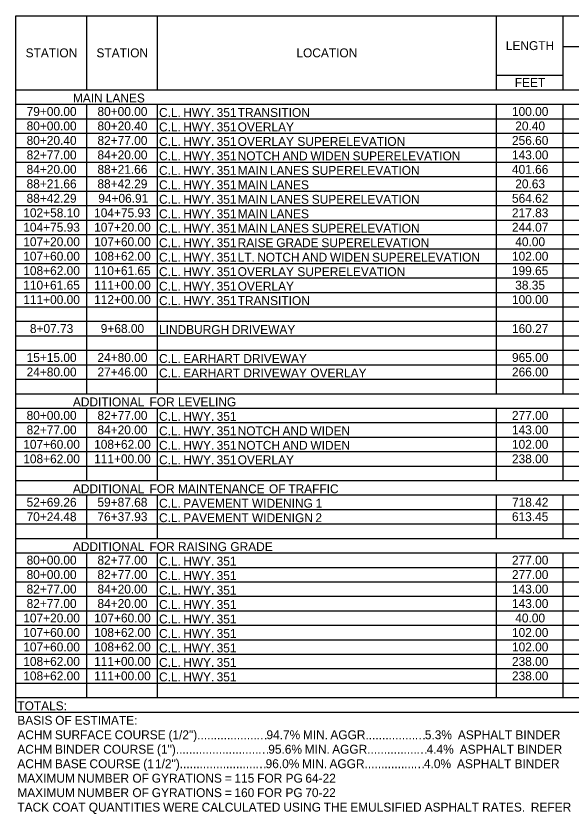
# Model space of a CAD drawing. Extents: x 1197542 to 1207068, y 230488 to 237324.
# Drawn here: x 1201719 to 1202093, y 231730 to 232267 of the extents above; entities that cross this region are included whole.
import ezdxf

# ---------------------------------------------------------------- set-up
doc = ezdxf.new("R2010")
doc.units = 0
doc.layers.add('Default', color=7, linetype='Continuous')

msp = doc.modelspace()

# ---------------------------------------------------------------- linework, layer by layer
at = {"layer": 'Default'}
for p, q in [((1201719.44, 232267.45), (1203261.96, 232267.45)), ((1201719.44, 231798.48), (1201719.44, 232267.45)), ((1201719.44, 231798.48), (1201719.44, 232267.45)), ((1201767.17, 232217.73), (1201767.17, 232267.45)), ((1201814.91, 232217.73), (1201814.91, 232267.45)), ((1202043.29, 232217.73), (1202043.29, 232267.45)), ((1202088.22, 232217.73), (1202088.22, 232267.45)), ((1202088.22, 232246.98), (1203261.96, 232246.98)), ((1202043.29, 232227.48), (1202088.22, 232227.48)), ((1202088.22, 232217.73), (1202088.22, 232227.48)), ((1201719.44, 232217.73), (1203261.96, 232217.73)), ((1202088.22, 232217.73), (1202223, 232217.73)), ((1201719.44, 232207.98), (1203261.96, 232207.98)), ((1201767.17, 232012.98), (1201767.17, 232207.98)), ((1201767.17, 232012.98), (1201767.17, 232207.98)), ((1201814.91, 232012.98), (1201814.91, 232207.98)), ((1201814.91, 232012.98), (1201814.91, 232207.98)), ((1202043.29, 232012.98), (1202043.29, 232207.98)), ((1202043.29, 232012.98), (1202043.29, 232207.98)), ((1202088.22, 232012.98), (1202088.22, 232207.98)), ((1202088.22, 232012.98), (1202088.22, 232207.98)), ((1201719.44, 232198.23), (1203261.96, 232198.23)), ((1201719.44, 232188.48), (1203261.96, 232188.48)), ((1201719.44, 232178.73), (1203261.96, 232178.73)), ((1201719.44, 232168.98), (1203261.96, 232168.98)), ((1201719.44, 232159.23), (1203261.96, 232159.23)), ((1201719.44, 232149.48), (1203261.96, 232149.48)), ((1201719.44, 232139.73), (1203261.96, 232139.73)), ((1201719.44, 232129.98), (1203261.96, 232129.98)), ((1201719.44, 232120.23), (1203261.96, 232120.23)), ((1201719.44, 232110.48), (1203261.96, 232110.48)), ((1201719.44, 232100.73), (1203261.96, 232100.73)), ((1201719.44, 232090.98), (1203261.96, 232090.98)), ((1201719.44, 232081.23), (1203261.96, 232081.23)), ((1201719.44, 232071.48), (1203261.96, 232071.48)), ((1201719.44, 232061.73), (1203261.96, 232061.73)), ((1201719.44, 232051.98), (1203261.96, 232051.98)), ((1201719.44, 232042.23), (1203261.96, 232042.23)), ((1201719.44, 232032.48), (1203261.96, 232032.48)), ((1201719.44, 232022.73), (1203261.96, 232022.73)), ((1201719.44, 232012.98), (1202992.4, 232012.98)), ((1201719.44, 232012.98), (1203261.96, 232012.98)), ((1201719.44, 232003.23), (1203261.96, 232003.23)), ((1201767.17, 231954.48), (1201767.17, 232003.23)), ((1201767.17, 231954.48), (1201767.17, 232003.23)), ((1201814.91, 231954.48), (1201814.91, 232003.23)), ((1201814.91, 231954.48), (1201814.91, 232003.23)), ((1202043.29, 231954.48), (1202043.29, 232003.23)), ((1202043.29, 231954.48), (1202043.29, 232003.23)), ((1202088.22, 231954.48), (1202088.22, 232003.23)), ((1202088.22, 231954.48), (1202088.22, 232003.23)), ((1201719.44, 231993.48), (1203261.96, 231993.48)), ((1201719.44, 231983.73), (1203261.96, 231983.73)), ((1201719.44, 231973.98), (1203261.96, 231973.98)), ((1201719.44, 231964.23), (1203261.96, 231964.23)), ((1201719.44, 231954.48), (1203261.96, 231954.48)), ((1201719.44, 231954.48), (1203261.96, 231954.48)), ((1201719.44, 231944.73), (1203261.96, 231944.73)), ((1201767.17, 231915.48), (1201767.17, 231944.73)), ((1201767.17, 231915.48), (1201767.17, 231944.73)), ((1201814.91, 231915.48), (1201814.91, 231944.73)), ((1201814.91, 231915.48), (1201814.91, 231944.73)), ((1202043.29, 231915.48), (1202043.29, 231944.73)), ((1202043.29, 231915.48), (1202043.29, 231944.73)), ((1202088.22, 231915.48), (1202088.22, 231944.73)), ((1202088.22, 231915.48), (1202088.22, 231944.73)), ((1201719.44, 231934.98), (1203261.96, 231934.98)), ((1201719.44, 231925.23), (1203261.96, 231925.23)), ((1201719.44, 231915.48), (1202992.4, 231915.48)), ((1201719.44, 231915.48), (1203261.96, 231915.48)), ((1201719.44, 231905.73), (1203261.96, 231905.73)), ((1201767.17, 231808.23), (1201767.17, 231905.73)), ((1201767.17, 231808.23), (1201767.17, 231905.73)), ((1201814.91, 231808.23), (1201814.91, 231905.73)), ((1201814.91, 231808.23), (1201814.91, 231905.73)), ((1202043.29, 231808.23), (1202043.29, 231905.73)), ((1202043.29, 231808.23), (1202043.29, 231905.73)), ((1202088.22, 231808.23), (1202088.22, 231905.73)), ((1202088.22, 231808.23), (1202088.22, 231905.73)), ((1201719.44, 231895.98), (1203261.96, 231895.98)), ((1201719.44, 231886.23), (1203261.96, 231886.23)), ((1201719.44, 231876.48), (1203261.96, 231876.48)), ((1201719.44, 231866.73), (1203261.96, 231866.73)), ((1201719.44, 231856.98), (1203261.96, 231856.98)), ((1201719.44, 231847.23), (1203261.96, 231847.23)), ((1201719.44, 231837.48), (1203261.96, 231837.48)), ((1201719.44, 231827.73), (1203261.96, 231827.73)), ((1201719.44, 231817.98), (1203261.96, 231817.98)), ((1201719.44, 231808.23), (1203261.96, 231808.23)), ((1201719.44, 231808.23), (1203261.96, 231808.23)), ((1201719.44, 231798.48), (1203261.96, 231798.48))]:
    msp.add_line(p, q, dxfattribs=at)

# ---------------------------------------------------------------- texts
for s, p in [('LENGTH', (1202049.52, 232244.47)), ('STATION', (1201725.96, 232239.59)), ('STATION', (1201773.7, 232239.59)), ('LOCATION', (1201908.41, 232239.59)), ('FEET', (1202055.55, 232219.6)), ('MAIN', (1201757.81, 232209.18)), (' LANES', (1201777.73, 232209.18)), ('79+00.00', (1201726.61, 232200.1)), ('80+00.00', (1201774.35, 232200.1)), ('C.L.', (1201815.84, 232199.43)), (' HWY.', (1201829.9, 232199.43)), (' 351', (1201852.44, 232199.43)), (' TRANSITION', (1201866.62, 232199.43)), ('100.00', (1202053.65, 232200.1)), ('80+00.00', (1201726.61, 232190.35)), ('80+20.40', (1201774.35, 232190.35)), ('C.L.', (1201815.84, 232189.68)), (' HWY.', (1201829.9, 232189.68)), (' 351', (1201852.44, 232189.68)), (' OVERLAY', (1201866.62, 232189.68)), ('20.40', (1202055.88, 232190.35)), ('80+20.40', (1201726.61, 232180.6)), ('82+77.00', (1201774.35, 232180.6)), ('C.L.', (1201815.84, 232179.93)), (' HWY.', (1201829.9, 232179.93)), (' 351', (1201852.44, 232179.93)), (' OVERLAY', (1201866.62, 232179.93)), (' SUPERELEVATION', (1201906.81, 232179.93)), ('256.60', (1202053.65, 232180.6)), ('82+77.00', (1201726.61, 232170.85)), ('84+20.00', (1201774.35, 232170.85)), ('C.L.', (1201815.84, 232170.18)), (' HWY.', (1201829.9, 232170.18)), (' 351', (1201852.44, 232170.18)), (' NOTCH', (1201866.62, 232170.18)), (' AND', (1201896.82, 232170.18)), (' WIDEN', (1201915.62, 232170.18)), (' SUPERELEVATION', (1201944.02, 232170.18)), ('143.00', (1202053.65, 232170.85)), ('84+20.00', (1201726.61, 232161.1)), ('88+21.66', (1201774.34, 232161.1)), ('401.66', (1202053.64, 232161.1)), ('C.L.', (1201815.84, 232160.43)), (' HWY.', (1201829.9, 232160.43)), (' 351', (1201852.44, 232160.43)), (' MAIN', (1201866.62, 232160.43)), (' LANES', (1201888.31, 232160.43)), (' SUPERELEVATION', (1201916.52, 232160.43)), ('88+21.66', (1201726.6, 232151.35)), ('88+42.29', (1201774.33, 232151.35)), ('C.L.', (1201815.84, 232150.68)), (' HWY.', (1201829.9, 232150.68)), (' 351', (1201852.44, 232150.68)), (' MAIN', (1201866.62, 232150.68)), (' LANES', (1201888.31, 232150.68)), ('20.63', (1202055.87, 232151.35)), ('88+42.29', (1201726.59, 232141.6)), ('94+06.91', (1201774.89, 232141.6)), ('C.L.', (1201815.84, 232140.93)), (' HWY.', (1201829.9, 232140.93)), (' 351', (1201852.44, 232140.93)), (' MAIN', (1201866.62, 232140.93)), (' LANES', (1201888.31, 232140.93)), (' SUPERELEVATION', (1201916.52, 232140.93)), ('564.62', (1202053.67, 232141.6)), ('102+58.10', (1201724.37, 232131.85)), ('104+75.93', (1201772.1, 232131.85)), ('C.L.', (1201815.84, 232131.18)), (' HWY.', (1201829.9, 232131.18)), (' 351', (1201852.44, 232131.18)), (' MAIN', (1201866.62, 232131.18)), (' LANES', (1201888.31, 232131.18)), ('217.83', (1202053.64, 232131.85)), ('104+75.93', (1201724.36, 232122.1)), ('107+20.00', (1201772.11, 232122.1)), ('C.L.', (1201815.84, 232121.43)), (' HWY.', (1201829.9, 232121.43)), (' 351', (1201852.44, 232121.43)), (' MAIN', (1201866.62, 232121.43)), (' LANES', (1201888.31, 232121.43)), (' SUPERELEVATION', (1201916.52, 232121.43)), ('244.07', (1202053.64, 232122.1)), ('107+20.00', (1201724.37, 232112.35)), ('107+60.00', (1201772.11, 232112.35)), ('C.L.', (1201815.84, 232111.68)), (' HWY.', (1201829.9, 232111.68)), (' 351', (1201852.44, 232111.68)), (' RAISE', (1201866.62, 232111.68)), (' GRADE', (1201892.58, 232111.68)), (' SUPERELEVATION', (1201923.01, 232111.68)), ('40.00', (1202055.88, 232112.35)), ('107+60.00', (1201724.37, 232102.6)), ('108+62.00', (1201772.11, 232102.6)), ('102.00', (1202053.65, 232102.6)), ('C.L.', (1201815.84, 232101.93)), (' HWY.', (1201829.9, 232101.93)), (' 351', (1201852.44, 232101.93)), (' LT.', (1201866.62, 232101.93)), (' NOTCH', (1201879.77, 232101.93)), (' AND', (1201909.98, 232101.93)), (' WIDEN', (1201928.77, 232101.93)), (' SUPERELEVATION', (1201957.17, 232101.93)), ('108+62.00', (1201724.37, 232092.85)), ('110+61.65', (1201772.08, 232092.85)), ('C.L.', (1201815.84, 232092.18)), (' HWY.', (1201829.9, 232092.18)), (' 351', (1201852.44, 232092.18)), (' OVERLAY', (1201866.62, 232092.18)), (' SUPERELEVATION', (1201906.81, 232092.18)), ('199.65', (1202053.61, 232092.85)), ('110+61.65', (1201724.34, 232083.1)), ('111+00.00', (1201772.11, 232083.1)), ('C.L.', (1201815.84, 232082.43)), (' HWY.', (1201829.9, 232082.43)), (' 351', (1201852.44, 232082.43)), (' OVERLAY', (1201866.62, 232082.43)), ('38.35', (1202055.85, 232083.1)), ('111+00.00', (1201724.37, 232073.35)), ('112+00.00', (1201772.11, 232073.35)), ('C.L.', (1201815.84, 232072.68)), (' HWY.', (1201829.9, 232072.68)), (' 351', (1201852.44, 232072.68)), (' TRANSITION', (1201866.62, 232072.68)), ('100.00', (1202053.65, 232073.35)), ('8+07.73', (1201728.84, 232053.85)), ('9+68.00', (1201776.58, 232053.85)), ('160.27', (1202053.64, 232053.85)), ('LINDBURGH', (1201815.84, 232053.18)), (' DRIVEWAY', (1201862.6, 232053.18)), ('15+15.00', (1201726.61, 232034.35)), ('24+80.00', (1201774.35, 232034.35)), ('C.L.', (1201815.84, 232033.68)), (' EARHART', (1201829.9, 232033.68)), (' DRIVEWAY', (1201870.43, 232033.68)), ('965.00', (1202053.65, 232034.35)), ('24+80.00', (1201726.61, 232024.6)), ('27+46.00', (1201774.35, 232024.6)), ('C.L.', (1201815.84, 232023.93)), (' EARHART', (1201829.9, 232023.93)), (' DRIVEWAY', (1201870.43, 232023.93)), (' OVERLAY', (1201915.54, 232023.93)), ('266.00', (1202053.65, 232024.6)), ('ADDITIONAL', (1201757.81, 232004.43)), (' FOR', (1201807.2, 232004.43)), (' LEVELING', (1201826.38, 232004.43)), ('80+00.00', (1201726.61, 231995.35)), ('82+77.00', (1201774.35, 231995.35)), ('C.L.', (1201815.84, 231994.68)), (' HWY.', (1201829.9, 231994.68)), (' 351', (1201852.44, 231994.68)), ('277.00', (1202053.65, 231995.35)), ('82+77.00', (1201726.61, 231985.6)), ('84+20.00', (1201774.35, 231985.6)), ('C.L.', (1201815.84, 231984.93)), (' HWY.', (1201829.9, 231984.93)), (' 351', (1201852.44, 231984.93)), (' NOTCH', (1201866.62, 231984.93)), (' AND', (1201896.82, 231984.93)), (' WIDEN', (1201915.62, 231984.93)), ('143.00', (1202053.65, 231985.6)), ('107+60.00', (1201724.37, 231975.85)), ('108+62.00', (1201772.11, 231975.85)), ('C.L.', (1201815.84, 231975.18)), (' HWY.', (1201829.9, 231975.18)), (' 351', (1201852.44, 231975.18)), (' NOTCH', (1201866.62, 231975.18)), (' AND', (1201896.82, 231975.18)), (' WIDEN', (1201915.62, 231975.18)), ('102.00', (1202053.65, 231975.85)), ('108+62.00', (1201724.37, 231966.1)), ('111+00.00', (1201772.11, 231966.1)), ('C.L.', (1201815.84, 231965.43)), (' HWY.', (1201829.9, 231965.43)), (' 351', (1201852.44, 231965.43)), (' OVERLAY', (1201866.62, 231965.43)), ('238.00', (1202053.65, 231966.1)), ('ADDITIONAL', (1201757.81, 231945.93)), (' FOR', (1201807.2, 231945.93)), (' MAINTENANCE', (1201826.38, 231945.93)), (' OF', (1201887.69, 231945.93)), (' TRAFFIC', (1201900.73, 231945.93)), ('52+69.26', (1201726.6, 231936.85)), ('59+87.68', (1201774.33, 231936.85)), ('C.L.', (1201815.84, 231936.18)), (' PAVEMENT', (1201829.9, 231936.18)), (' WIDENING', (1201876.25, 231936.18)), (' 1', (1201919.11, 231936.18)), ('718.42', (1202053.67, 231936.85)), ('70+24.48', (1201726.59, 231927.1)), ('76+37.93', (1201774.34, 231927.1)), ('C.L.', (1201815.84, 231926.43)), (' PAVEMENT', (1201829.9, 231926.43)), (' WIDENIGN', (1201876.25, 231926.43)), (' 2', (1201918.96, 231926.43)), ('613.45', (1202053.61, 231927.1)), ('ADDITIONAL', (1201757.81, 231906.93)), (' FOR', (1201807.2, 231906.93)), (' RAISING', (1201826.38, 231906.93)), (' GRADE', (1201861.67, 231906.93)), ('80+00.00', (1201726.61, 231897.85)), ('82+77.00', (1201774.35, 231897.85)), ('277.00', (1202053.65, 231897.85)), ('C.L.', (1201815.84, 231897.18)), (' HWY.', (1201829.9, 231897.18)), (' 351', (1201852.44, 231897.18)), ('80+00.00', (1201726.61, 231888.1)), ('82+77.00', (1201774.35, 231888.1)), ('C.L.', (1201815.84, 231887.43)), (' HWY.', (1201829.9, 231887.43)), (' 351', (1201852.44, 231887.43)), ('277.00', (1202053.65, 231888.1)), ('82+77.00', (1201726.61, 231878.35)), ('84+20.00', (1201774.35, 231878.35)), ('C.L.', (1201815.84, 231877.68)), (' HWY.', (1201829.9, 231877.68)), (' 351', (1201852.44, 231877.68)), ('143.00', (1202053.65, 231878.35)), ('82+77.00', (1201726.61, 231868.6)), ('84+20.00', (1201774.35, 231868.6)), ('C.L.', (1201815.84, 231867.93)), (' HWY.', (1201829.9, 231867.93)), (' 351', (1201852.44, 231867.93)), ('143.00', (1202053.65, 231868.6)), ('107+20.00', (1201724.37, 231858.85)), ('107+60.00', (1201772.11, 231858.85)), ('C.L.', (1201815.84, 231858.18)), (' HWY.', (1201829.9, 231858.18)), (' 351', (1201852.44, 231858.18)), ('40.00', (1202055.88, 231858.85)), ('107+60.00', (1201724.37, 231849.1)), ('108+62.00', (1201772.11, 231849.1)), ('C.L.', (1201815.84, 231848.43)), (' HWY.', (1201829.9, 231848.43)), (' 351', (1201852.44, 231848.43)), ('102.00', (1202053.65, 231849.1)), ('107+60.00', (1201724.37, 231839.35)), ('108+62.00', (1201772.11, 231839.35)), ('C.L.', (1201815.84, 231838.68)), (' HWY.', (1201829.9, 231838.68)), (' 351', (1201852.44, 231838.68)), ('102.00', (1202053.65, 231839.35)), ('108+62.00', (1201724.37, 231829.6)), ('111+00.00', (1201772.11, 231829.6)), ('C.L.', (1201815.84, 231828.93)), (' HWY.', (1201829.9, 231828.93)), (' 351', (1201852.44, 231828.93)), ('238.00', (1202053.65, 231829.6)), ('108+62.00', (1201724.37, 231819.85)), ('111+00.00', (1201772.11, 231819.85)), ('C.L.', (1201815.84, 231819.18)), (' HWY.', (1201829.9, 231819.18)), (' 351', (1201852.44, 231819.18)), ('238.00', (1202053.65, 231819.85)), ('TOTALS:', (1201720.37, 231799.68)), ('BASIS', (1201720.37, 231789.93)), (' OF', (1201743.66, 231789.93)), (' ESTIMATE:', (1201756.71, 231789.93)), ('ACHM', (1201720.37, 231780.18)), (' SURFACE', (1201743.46, 231780.18)), (' COURSE', (1201783.73, 231780.18)), (' (1/2")..................', (1201819.97, 231780.18)), ('94.7%', (1201888.23, 231780.18)), (' MIN.', (1201910.54, 231780.18)), (' AGGR...............', (1201929.06, 231780.18)), ('5.3%', (1201994.92, 231780.18)), ('  ASPHALT', (1202012.75, 231780.18)), (' BINDER', (1202053.74, 231780.18)), ('…', (1201881.13, 231780.18)), ('…', (1201987.81, 231780.18)), ('ACHM', (1201720.37, 231770.43)), (' BINDER', (1201743.46, 231770.43)), (' COURSE', (1201776, 231770.43)), (' (1").........................', (1201812.24, 231770.43)), ('95.6%', (1201889.43, 231770.43)), (' MIN.', (1201911.74, 231770.43)), (' AGGR...............', (1201930.26, 231770.43)), ('4.4%', (1201996.12, 231770.43)), ('  ASPHALT', (1202013.96, 231770.43)), (' BINDER', (1202054.94, 231770.43)), ('…', (1201882.33, 231770.43)), ('…', (1201989.02, 231770.43)), ('ACHM', (1201720.37, 231760.68)), (' BASE', (1201743.46, 231760.68)), (' COURSE', (1201766.75, 231760.68)), (' (1', (1201802.99, 231760.68)), (' 1/2").......................', (1201810.89, 231760.68)), ('96.0%', (1201887.64, 231760.68)), (' MIN.', (1201909.96, 231760.68)), (' AGGR...............', (1201928.47, 231760.68)), ('4.0%', (1201994.33, 231760.68)), ('  ASPHALT', (1202012.17, 231760.68)), (' BINDER', (1202053.16, 231760.68)), ('…', (1201880.54, 231760.68)), ('…', (1201987.23, 231760.68)), ('MAXIMUM', (1201720.37, 231750.93)), (' NUMBER', (1201758.66, 231750.93)), (' OF', (1201795.67, 231750.93)), (' GYRATIONS', (1201808.71, 231750.93)), (' =', (1201857.93, 231750.93)), (' 115', (1201864.42, 231750.93)), (' FOR', (1201879.75, 231750.93)), (' PG', (1201898.87, 231750.93)), (' 64-22', (1201912.23, 231750.93)), ('MAXIMUM', (1201720.37, 231741.18)), (' NUMBER', (1201758.66, 231741.18)), (' OF', (1201795.67, 231741.18)), (' GYRATIONS', (1201808.71, 231741.18)), (' =', (1201857.93, 231741.18)), (' 160', (1201864.42, 231741.18)), (' FOR', (1201879.69, 231741.18)), (' PG', (1201898.8, 231741.18)), (' 70-22', (1201912.16, 231741.18)), ('TACK', (1201720.37, 231731.43)), (' COAT', (1201741.82, 231731.43)), (' QUANTITIES', (1201766.25, 231731.43)), (' WERE', (1201816.36, 231731.43)), (' CALCULATED', (1201842.32, 231731.43)), (' USING', (1201897.34, 231731.43)), (' THE', (1201924.56, 231731.43)), (' EMULSIFIED', (1201942.47, 231731.43)), (' ASPHALT', (1201992.57, 231731.43)), (' RATES.', (1202031.32, 231731.43)), ('  REFER', (1202061.92, 231731.43))]:
    msp.add_text(s, height=6, dxfattribs=at).set_placement(p)

doc.saveas('drawing.dxf')
